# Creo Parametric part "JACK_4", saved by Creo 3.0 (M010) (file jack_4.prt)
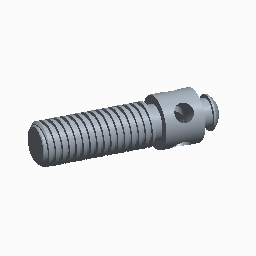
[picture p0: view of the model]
Units: millimeter Newton Second (mmNs); MM, TONNE, SECS

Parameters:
  PLACEMENT = "EXTERNAL"

Other parameters: MINOR_DIAMETER, PITCH

Created from: MMNS_PART_SOLID.PRT

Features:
  1. datum plane "RIGHT"
  2. datum plane "TOP"
  3. datum plane "FRONT"
  4. coordinate system
  5. protrusion
  6. chamfer
  7. pattern
  8. cut
  9. cut
  10. cut
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
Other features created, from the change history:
  planar section "A3-1"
